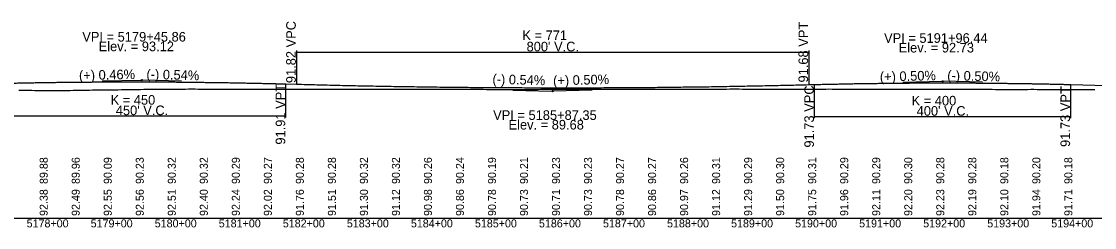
# Model space of a CAD drawing. Extents: x 2121671 to 2169879, y 557274 to 599957.
# Drawn here: x 2147326 to 2149002, y 592693 to 593014 of the extents above; entities that cross this region are included whole.
import ezdxf

# ---------------------------------------------------------------- set-up
doc = ezdxf.new("R2010")
doc.units = 0
for name, color, linetype in [('RD_DDB_GradeTX', 7, 'Continuous'), ('RD_DDB_Profile_EX', 7, 'Continuous'), ('RD_DDB_Profile_Lbl', 7, 'Continuous'), ('RD_DDB_Profile_PR', 7, 'Continuous'), ('RD_DDB_StaTX', 7, 'Continuous'), ('RD_DDB_StripGrade', 7, 'Continuous'), ('RD_DDB_VCLbl', 7, 'Continuous'), ('RD_GPK_Profile_Cell', 7, 'Continuous')]:
    doc.layers.add(name, color=color, linetype=linetype)

msp = doc.modelspace()

# ---------------------------------------------------------------- linework, layer by layer
at = {"layer": 'RD_DDB_GradeTX'}
for p, q in [((2147452.1, 592921.6), (2147513.1, 592923)), ((2147576.1, 592921.4), (2147515.1, 592923)), ((2148093.6, 592907.5), (2148154.6, 592905.9)), ((2148217.6, 592907.4), (2148156.6, 592905.9)), ((2148702.7, 592919.6), (2148763.7, 592921.1)), ((2148826.7, 592919.6), (2148765.7, 592921.1))]:
    msp.add_line(p, q, dxfattribs=at)
for centre in [(2147514.1, 592923.1), (2148764.7, 592921.1), (2148155.6, 592905.9)]:
    msp.add_circle(centre, 1, dxfattribs=at)
at = {"layer": 'RD_DDB_Profile_EX'}
for points in [[(2147322.2, 592907.3), (2147327.2, 592907.2), (2147332.2, 592907.1), (2147337.2, 592907.1), (2147342.2, 592907.1), (2147347.2, 592907), (2147352.2, 592907), (2147357.2, 592906.9), (2147362.2, 592906.9), (2147367.2, 592906.9), (2147372.2, 592906.8), (2147377.2, 592906.8), (2147382.2, 592906.8), (2147387.2, 592906.7), (2147392.2, 592906.8), (2147397.2, 592906.9), (2147402.2, 592907), (2147407.2, 592907.1), (2147412.2, 592907.2), (2147417.2, 592907.3), (2147422.2, 592907.4), (2147427.2, 592907.5), (2147432.2, 592907.5), (2147437.2, 592907.6), (2147442.2, 592907.7), (2147447.2, 592907.7), (2147452.2, 592907.8), (2147457.2, 592907.8), (2147462.2, 592907.9), (2147467.2, 592907.9), (2147472.2, 592908), (2147477.2, 592908), (2147482.2, 592908.1), (2147487.2, 592908.2), (2147492.2, 592908.3), (2147497.2, 592908.3), (2147502.2, 592908.4), (2147507.2, 592908.5), (2147512.2, 592908.5), (2147517.2, 592908.6), (2147522.2, 592908.6), (2147527.2, 592908.7), (2147532.2, 592908.7), (2147537.2, 592908.8), (2147542.2, 592908.8), (2147547.2, 592908.9), (2147552.2, 592908.9), (2147557.2, 592909), (2147562.2, 592909), (2147567.2, 592909), (2147572.2, 592909.1), (2147577.2, 592909.1), (2147582.2, 592909.1), (2147587.2, 592909.2), (2147592.2, 592909.2), (2147597.2, 592909.2), (2147602.2, 592909.1), (2147607.2, 592909.1), (2147612.2, 592909.1), (2147617.2, 592909.1), (2147622.2, 592909), (2147627.2, 592909), (2147632.2, 592909), (2147637.2, 592909), (2147642.2, 592909), (2147647.2, 592909), (2147652.2, 592908.9), (2147657.2, 592908.9), (2147662.2, 592908.9), (2147667.2, 592908.9), (2147672.2, 592908.9), (2147677.2, 592908.9), (2147682.2, 592908.9), (2147687.2, 592908.9), (2147692.2, 592908.9), (2147697.2, 592908.9), (2147702.2, 592908.9), (2147707.2, 592908.9), (2147712.2, 592908.8)], [(2147712.2, 592908.8), (2147717.2, 592908.8), (2147722.2, 592908.8), (2147727.2, 592908.8), (2147732.2, 592908.8), (2147737.2, 592908.7), (2147742.2, 592908.7), (2147747.2, 592908.7), (2147752.2, 592908.7), (2147757.2, 592908.8), (2147762.2, 592908.8), (2147767.2, 592908.8), (2147772.2, 592908.9), (2147777.2, 592908.9), (2147782.2, 592909), (2147787.2, 592909), (2147792.2, 592909), (2147797.2, 592909), (2147802.2, 592909), (2147807.2, 592909), (2147812.2, 592908.9), (2147817.2, 592908.9), (2147822.2, 592908.9), (2147827.2, 592908.8), (2147832.2, 592908.8), (2147837.2, 592908.9), (2147842.2, 592908.9), (2147847.2, 592908.9), (2147852.2, 592909), (2147857.2, 592909), (2147862.2, 592909), (2147867.2, 592909.1), (2147872.2, 592909.1), (2147877.2, 592909.1), (2147882.2, 592909.1), (2147887.2, 592909.1), (2147892.2, 592909.1), (2147897.2, 592909.1), (2147902.2, 592909.1), (2147907.2, 592909.1), (2147912.2, 592909.1), (2147917.2, 592909.1), (2147922.2, 592909.1), (2147927.2, 592909), (2147932.2, 592909), (2147937.2, 592909), (2147942.2, 592908.9), (2147947.2, 592908.9), (2147952.2, 592908.8), (2147957.2, 592908.8), (2147962.2, 592908.8), (2147967.2, 592908.8), (2147972.2, 592908.8), (2147977.2, 592908.7), (2147982.2, 592908.7), (2147987.2, 592908.7), (2147992.2, 592908.7), (2147997.2, 592908.7), (2148002.2, 592908.7), (2148007.2, 592908.7), (2148012.2, 592908.7), (2148017.2, 592908.6), (2148022.2, 592908.6), (2148027.2, 592908.6), (2148032.2, 592908.6), (2148037.2, 592908.6), (2148042.2, 592908.6), (2148047.2, 592908.6), (2148052.2, 592908.5), (2148057.2, 592908.5), (2148062.2, 592908.5), (2148067.2, 592908.4), (2148072.2, 592908.4), (2148077.2, 592908.4), (2148082.2, 592908.4), (2148087.2, 592908.4), (2148092.2, 592908.4), (2148097.2, 592908.4), (2148102.2, 592908.4), (2148107.2, 592908.5), (2148112.2, 592908.5), (2148117.2, 592908.5), (2148122.2, 592908.5), (2148127.2, 592908.5), (2148132.2, 592908.5), (2148137.2, 592908.6), (2148142.2, 592908.6), (2148147.2, 592908.6), (2148152.2, 592908.6), (2148157.2, 592908.6), (2148162.2, 592908.6), (2148167.2, 592908.6), (2148172.2, 592908.6), (2148177.2, 592908.6), (2148182.2, 592908.6), (2148187.2, 592908.6), (2148192.2, 592908.6), (2148197.2, 592908.6), (2148202.2, 592908.6), (2148207.2, 592908.6), (2148212.2, 592908.6)], [(2148212.2, 592908.6), (2148217.2, 592908.6), (2148222.2, 592908.6), (2148227.2, 592908.6), (2148232.2, 592908.6), (2148237.2, 592908.6), (2148242.2, 592908.7), (2148247.2, 592908.7), (2148252.2, 592908.7), (2148257.2, 592908.7), (2148262.2, 592908.8), (2148267.2, 592908.8), (2148272.2, 592908.8), (2148277.2, 592908.9), (2148282.2, 592908.9), (2148287.2, 592908.9), (2148292.2, 592908.9), (2148297.2, 592908.9), (2148302.2, 592908.8), (2148307.2, 592908.8), (2148312.2, 592908.8), (2148317.2, 592908.8), (2148322.2, 592908.8), (2148327.2, 592908.8), (2148332.2, 592908.8), (2148337.2, 592908.8), (2148342.2, 592908.8), (2148347.2, 592908.8), (2148352.2, 592908.8), (2148357.2, 592908.7), (2148362.2, 592908.7), (2148367.2, 592908.7), (2148372.2, 592908.8), (2148377.2, 592908.8), (2148382.2, 592908.8), (2148387.2, 592908.8), (2148392.2, 592908.8), (2148397.2, 592908.8), (2148402.2, 592908.8), (2148407.2, 592908.9), (2148412.2, 592908.9), (2148417.2, 592909), (2148422.2, 592909.1), (2148427.2, 592909.1), (2148432.2, 592909.2), (2148437.2, 592909.3), (2148442.2, 592909.2), (2148447.2, 592909.2), (2148452.2, 592909.1), (2148457.2, 592909.1), (2148462.2, 592909), (2148467.2, 592908.9), (2148472.2, 592908.9), (2148477.2, 592908.8), (2148482.2, 592908.8), (2148487.2, 592908.8), (2148492.2, 592908.9), (2148497.2, 592908.9), (2148502.2, 592908.9), (2148507.2, 592908.9), (2148512.2, 592908.9), (2148517.2, 592909), (2148522.2, 592908.9), (2148527.2, 592909), (2148532.2, 592909), (2148537.2, 592909), (2148542.2, 592909), (2148547.2, 592909), (2148552.2, 592909), (2148557.2, 592909), (2148562.2, 592909), (2148567.2, 592909), (2148572.2, 592909.1), (2148577.2, 592909.1), (2148582.2, 592909.1), (2148587.2, 592909.2), (2148592.2, 592909.1), (2148597.2, 592909.1), (2148602.2, 592909), (2148607.2, 592909), (2148612.2, 592908.9), (2148617.2, 592908.9), (2148622.2, 592908.9), (2148627.2, 592908.8), (2148632.2, 592908.8), (2148637.2, 592908.9), (2148642.2, 592908.9), (2148647.2, 592908.9), (2148652.2, 592908.9), (2148657.2, 592908.9), (2148662.2, 592908.9), (2148667.2, 592908.9), (2148672.2, 592908.9), (2148677.2, 592908.9), (2148682.2, 592909), (2148687.2, 592909), (2148692.2, 592909), (2148697.2, 592909), (2148702.2, 592909), (2148707.2, 592909), (2148712.2, 592909)], [(2148712.2, 592909), (2148717.2, 592909), (2148722.2, 592908.9), (2148727.2, 592908.9), (2148732.2, 592908.9), (2148737.2, 592908.8), (2148742.2, 592908.8), (2148747.2, 592908.8), (2148752.2, 592908.8), (2148757.2, 592908.8), (2148762.2, 592908.8), (2148767.2, 592908.9), (2148772.2, 592908.9), (2148777.2, 592908.9), (2148782.2, 592909), (2148787.2, 592909), (2148792.2, 592909), (2148797.2, 592909), (2148802.2, 592909), (2148807.2, 592909), (2148812.2, 592909), (2148817.2, 592908.9), (2148822.2, 592908.8), (2148827.2, 592908.8), (2148832.2, 592908.7), (2148837.2, 592908.7), (2148842.2, 592908.6), (2148847.2, 592908.5), (2148852.2, 592908.5), (2148857.2, 592908.4), (2148862.2, 592908.4), (2148867.2, 592908.4), (2148872.2, 592908.3), (2148877.2, 592908.3), (2148882.2, 592908.3), (2148887.2, 592908.3), (2148892.2, 592908.4), (2148897.2, 592908.5), (2148902.2, 592908.6), (2148907.2, 592908.6), (2148912.2, 592908.5), (2148917.2, 592908.5), (2148922.2, 592908.5), (2148927.2, 592908.4), (2148932.2, 592908.4), (2148937.2, 592908.4), (2148942.2, 592908.4), (2148947.2, 592908.4), (2148952.2, 592908.4), (2148957.2, 592908.4), (2148962.2, 592908.4), (2148967.2, 592908.4), (2148972.2, 592908.3), (2148977.2, 592908.3), (2148982.2, 592908.3), (2148987.2, 592908.4), (2148992.2, 592908.4), (2148997.2, 592908.4), (2149002.2, 592908.4)]]:
    msp.add_lwpolyline(points, dxfattribs=at)
at = {"layer": 'RD_DDB_Profile_PR'}
for p, q in [((2147739.1, 592917), (2147755.6, 592916.6)), ((2148555.6, 592915.9), (2148564.7, 592916.1)), ((2148964.7, 592916.1), (2149161.5, 592911.2))]:
    msp.add_line(p, q, dxfattribs=at)
for points in [[(2147289.1, 592917.9), (2147298.1, 592918.1), (2147307.1, 592918.3), (2147316.1, 592918.4), (2147325.1, 592918.6), (2147334.1, 592918.8), (2147343.1, 592918.9), (2147352.1, 592919.1), (2147361.1, 592919.2), (2147370.1, 592919.4), (2147379.1, 592919.5), (2147388.1, 592919.6), (2147397.1, 592919.7), (2147406.1, 592919.8), (2147415.1, 592919.9), (2147424.1, 592920), (2147433.1, 592920), (2147442.1, 592920.1), (2147451.1, 592920.2), (2147460.1, 592920.2), (2147469.1, 592920.2), (2147478.1, 592920.3), (2147487.1, 592920.3), (2147496.1, 592920.3), (2147505.1, 592920.3), (2147514.1, 592920.3), (2147523.1, 592920.2), (2147532.1, 592920.2), (2147541.1, 592920.2), (2147550.1, 592920.1), (2147559.1, 592920.1), (2147568.1, 592920), (2147577.1, 592919.9), (2147586.1, 592919.8), (2147595.1, 592919.7), (2147604.1, 592919.6), (2147613.1, 592919.5), (2147622.1, 592919.4), (2147631.1, 592919.3), (2147640.1, 592919.1), (2147649.1, 592919), (2147658.1, 592918.8), (2147667.1, 592918.7), (2147676.1, 592918.5), (2147685.1, 592918.3), (2147694.1, 592918.1), (2147703.1, 592917.9), (2147712.1, 592917.7), (2147721.1, 592917.5), (2147730.1, 592917.3), (2147739.1, 592917)], [(2147755.6, 592916.6), (2147771.6, 592916.2), (2147787.6, 592915.8), (2147803.6, 592915.4), (2147819.6, 592915), (2147835.6, 592914.6), (2147851.6, 592914.3), (2147867.6, 592914), (2147883.6, 592913.7), (2147899.6, 592913.4), (2147915.6, 592913.1), (2147931.6, 592912.9), (2147947.6, 592912.6), (2147963.6, 592912.4), (2147979.6, 592912.2), (2147995.6, 592912), (2148011.6, 592911.8), (2148027.6, 592911.7), (2148043.6, 592911.6), (2148059.6, 592911.4), (2148075.6, 592911.3), (2148091.6, 592911.2), (2148107.6, 592911.2), (2148123.6, 592911.1), (2148139.6, 592911.1), (2148155.6, 592911), (2148171.6, 592911), (2148187.6, 592911), (2148203.6, 592911.1), (2148219.6, 592911.1), (2148235.6, 592911.2), (2148251.6, 592911.3), (2148267.6, 592911.4), (2148283.6, 592911.5), (2148299.6, 592911.6), (2148315.6, 592911.7), (2148331.6, 592911.9), (2148347.6, 592912.1), (2148363.6, 592912.3), (2148379.6, 592912.5), (2148395.6, 592912.7), (2148411.6, 592912.9), (2148427.6, 592913.2), (2148443.6, 592913.5), (2148459.6, 592913.8), (2148475.6, 592914.1), (2148491.6, 592914.4), (2148507.6, 592914.8), (2148523.6, 592915.1), (2148539.6, 592915.5), (2148555.6, 592915.9)], [(2148564.7, 592916.1), (2148572.7, 592916.3), (2148580.7, 592916.5), (2148588.7, 592916.7), (2148596.7, 592916.8), (2148604.7, 592917), (2148612.7, 592917.2), (2148620.7, 592917.3), (2148628.7, 592917.5), (2148636.7, 592917.6), (2148644.7, 592917.7), (2148652.7, 592917.8), (2148660.7, 592917.9), (2148668.7, 592918), (2148676.7, 592918.1), (2148684.7, 592918.2), (2148692.7, 592918.3), (2148700.7, 592918.4), (2148708.7, 592918.4), (2148716.7, 592918.5), (2148724.7, 592918.5), (2148732.7, 592918.6), (2148740.7, 592918.6), (2148748.7, 592918.6), (2148756.7, 592918.6), (2148764.7, 592918.6), (2148772.7, 592918.6), (2148780.7, 592918.6), (2148788.7, 592918.6), (2148796.7, 592918.6), (2148804.7, 592918.5), (2148812.7, 592918.5), (2148820.7, 592918.4), (2148828.7, 592918.4), (2148836.7, 592918.3), (2148844.7, 592918.2), (2148852.7, 592918.1), (2148860.7, 592918), (2148868.7, 592917.9), (2148876.7, 592917.8), (2148884.7, 592917.7), (2148892.7, 592917.6), (2148900.7, 592917.5), (2148908.7, 592917.3), (2148916.7, 592917.2), (2148924.7, 592917), (2148932.7, 592916.9), (2148940.7, 592916.7), (2148948.7, 592916.5), (2148956.7, 592916.3), (2148964.7, 592916.1)]]:
    msp.add_spline(points, degree=3, dxfattribs=at)
at = {"layer": 'RD_DDB_VCLbl'}
for p, q in [((2147755.6, 592969.1), (2147755.6, 592916.6)), ((2147755.6, 592966.6), (2148555.6, 592966.6)), ((2148555.6, 592969.1), (2148555.6, 592915.9)), ((2147739.1, 592864.5), (2147739.1, 592917)), ((2148564.7, 592863.6), (2148564.7, 592916.1)), ((2148964.7, 592863.6), (2148964.7, 592916.1)), ((2147289.1, 592867), (2147739.1, 592867)), ((2148564.7, 592866.1), (2148964.7, 592866.1))]:
    msp.add_line(p, q, dxfattribs=at)
at = {"layer": 'RD_GPK_Profile_Cell'}
msp.add_line((2146668.2, 592707.5), (2151268.2, 592707.5), dxfattribs=at)
msp.add_line((2146668.2, 592707.5), (2151268.2, 592707.5), dxfattribs=at)

# ---------------------------------------------------------------- texts
at = {"layer": 'RD_DDB_GradeTX'}
for s, rotation, p in [('(+) 0.46%', 1.3258, (2147416.2, 592922.8)), ('(-) 0.54%', 358.4628, (2147521.2, 592924.9)), ('(-) 0.50%', 358.5698, (2148771.7, 592922.9)), ('(-) 0.54%', 358.4628, (2148061.5, 592917.2)), ('(+) 0.50%', 1.4356, (2148156.5, 592914.7)), ('(+) 0.50%', 1.4356, (2148666.8, 592920.7))]:
    msp.add_text(s, height=15, rotation=rotation, dxfattribs=at).set_placement(p)
at = {"layer": 'RD_DDB_Profile_Lbl'}
for s, p in [('VPI = 5179+45.86', (2147421.2, 592983.1)), ('VPI = 5191+96.44', (2148673.2, 592981.1)), ('Elev. = 93.12', (2147446.7, 592968.1)), ('Elev. = 92.73', (2148696, 592966.1)), ('VPI = 5185+87.35', (2148062.8, 592860.9)), ('Elev. = 89.68', (2148086.8, 592845.9))]:
    msp.add_text(s, height=15, dxfattribs=at).set_placement(p)
at = {"layer": 'RD_DDB_StaTX'}
for s, p in [('5178+00', (2147334.3, 592693.2)), ('5179+00', (2147434.3, 592693.2)), ('5180+00', (2147534.3, 592693.2)), ('5181+00', (2147634.3, 592693.2)), ('5182+00', (2147734.3, 592693.2)), ('5183+00', (2147834.3, 592693.2)), ('5184+00', (2147934.3, 592693.2)), ('5185+00', (2148034.3, 592693.2)), ('5186+00', (2148134.3, 592693.2)), ('5187+00', (2148234.3, 592693.2)), ('5188+00', (2148334.3, 592693.2)), ('5189+00', (2148434.3, 592693.2)), ('5190+00', (2148534.3, 592693.2)), ('5191+00', (2148634.3, 592693.2)), ('5192+00', (2148734.3, 592693.2)), ('5193+00', (2148834.3, 592693.2)), ('5194+00', (2148934.3, 592693.2))]:
    msp.add_text(s, height=12.5, dxfattribs=at).set_placement(p)
at = {"layer": 'RD_DDB_StripGrade'}
for s, height, p in [('91.82 VPC', 15, (2147754.6, 592918.2)), ('91.68 VPT', 15, (2148554.6, 592919.2)), ('91.91 VPT', 15, (2147738.1, 592822.3)), ('91.73 VPC', 15, (2148563.7, 592817.7)), ('91.73 VPT', 15, (2148963.7, 592818.7)), ('89.88', 12.5, (2147367.2, 592760.9)), ('89.96', 12.5, (2147417.2, 592760.9)), ('90.09', 12.5, (2147467.2, 592760.9)), ('90.23', 12.5, (2147517.2, 592760.9)), ('90.32', 12.5, (2147567.2, 592760.9)), ('90.32', 12.5, (2147617.2, 592760.9)), ('90.29', 12.5, (2147667.2, 592760.9)), ('90.27', 12.5, (2147717.2, 592760.9)), ('90.28', 12.5, (2147767.2, 592760.9)), ('90.28', 12.5, (2147817.2, 592760.9)), ('90.32', 12.5, (2147867.2, 592760.9)), ('90.32', 12.5, (2147917.2, 592760.9)), ('90.26', 12.5, (2147967.2, 592760.9)), ('90.24', 12.5, (2148017.2, 592760.9)), ('90.19', 12.5, (2148067.2, 592760.9)), ('90.21', 12.5, (2148117.2, 592760.9)), ('90.23', 12.5, (2148167.2, 592760.9)), ('90.23', 12.5, (2148217.2, 592760.9)), ('90.27', 12.5, (2148267.2, 592760.9)), ('90.27', 12.5, (2148317.2, 592760.9)), ('90.26', 12.5, (2148367.2, 592760.9)), ('90.31', 12.5, (2148417.2, 592760.9)), ('90.29', 12.5, (2148467.2, 592760.9)), ('90.30', 12.5, (2148517.2, 592760.9)), ('90.31', 12.5, (2148567.2, 592760.9)), ('90.29', 12.5, (2148617.2, 592760.9)), ('90.29', 12.5, (2148667.2, 592760.9)), ('90.30', 12.5, (2148717.2, 592760.9)), ('90.28', 12.5, (2148767.2, 592760.9)), ('90.28', 12.5, (2148817.2, 592760.9)), ('90.18', 12.5, (2148867.2, 592760.9)), ('90.20', 12.5, (2148917.2, 592760.9)), ('90.18', 12.5, (2148967.2, 592760.9)), ('92.38', 12.5, (2147367.2, 592711)), ('92.49', 12.5, (2147417.2, 592711)), ('92.55', 12.5, (2147467.2, 592711)), ('92.56', 12.5, (2147517.2, 592711)), ('92.51', 12.5, (2147567.2, 592711)), ('92.40', 12.5, (2147617.2, 592711)), ('92.24', 12.5, (2147667.2, 592711)), ('92.02', 12.5, (2147717.2, 592711)), ('91.76', 12.5, (2147767.2, 592711)), ('91.51', 12.5, (2147817.2, 592711)), ('91.30', 12.5, (2147867.2, 592711)), ('91.12', 12.5, (2147917.2, 592711)), ('90.98', 12.5, (2147967.2, 592711)), ('90.86', 12.5, (2148017.2, 592711)), ('90.78', 12.5, (2148067.2, 592711)), ('90.73', 12.5, (2148117.2, 592711)), ('90.71', 12.5, (2148167.2, 592711)), ('90.73', 12.5, (2148217.2, 592711)), ('90.78', 12.5, (2148267.2, 592711)), ('90.86', 12.5, (2148317.2, 592711)), ('90.97', 12.5, (2148367.2, 592711)), ('91.12', 12.5, (2148417.2, 592711)), ('91.29', 12.5, (2148467.2, 592711)), ('91.50', 12.5, (2148517.2, 592711)), ('91.75', 12.5, (2148567.2, 592711)), ('91.96', 12.5, (2148617.2, 592711)), ('92.11', 12.5, (2148667.2, 592711)), ('92.20', 12.5, (2148717.2, 592711)), ('92.23', 12.5, (2148767.2, 592711)), ('92.19', 12.5, (2148817.2, 592711)), ('92.10', 12.5, (2148867.2, 592711)), ('91.94', 12.5, (2148917.2, 592711)), ('91.71', 12.5, (2148967.2, 592711))]:
    msp.add_text(s, height=height, rotation=90, dxfattribs=at).set_placement(p)
at = {"layer": 'RD_DDB_VCLbl'}
for s, p in [('K = 771', (2148108.5, 592985.4)), ("800' V.C.", (2148115, 592967.8)), ('K = 450', (2147465.4, 592884.6)), ('K = 400', (2148716.2, 592883.4)), ("450' V.C.", (2147473.5, 592868.3)), ("400' V.C.", (2148724.1, 592867.4))]:
    msp.add_text(s, height=15, dxfattribs=at).set_placement(p)

doc.saveas('drawing.dxf')
